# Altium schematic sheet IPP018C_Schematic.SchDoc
size 558 x 431 mm; Date: Not shown in title block; ApprovedBy: Not shown in title block; CheckedBy: Not shown in title block; Author: Not shown in title block; CompanyName: Not shown in title block; DrawnBy: Brandon Beader; Engineer: Not shown in title block; Organization: Not shown in title block; Address1: Not shown in title block; Address2: Not shown in title block; Address3: Not shown in title block; Address4: Not shown in title block; DocumentNumber: 2; Revision: Use project parameter SCH_Rev; SheetNumber: 1; SheetTotal: 2; PageSetup: Record=PageOptions¦CenterHorizontal=True¦CenterVertical=True¦PrintScale=1.00¦XCorrection=1.00¦YCorrection=1.00¦PrintKind=0¦BorderSize=5000000¦LeftOffset=0¦BottomOffset=0¦Orientation=2¦PaperLength=1000¦PaperWidth=1000¦Scale=100¦PaperSource=15¦PrintQuality=600¦MediaType=1¦DitherType=10¦PaperKind=Letter¦PrintScaleMode=1
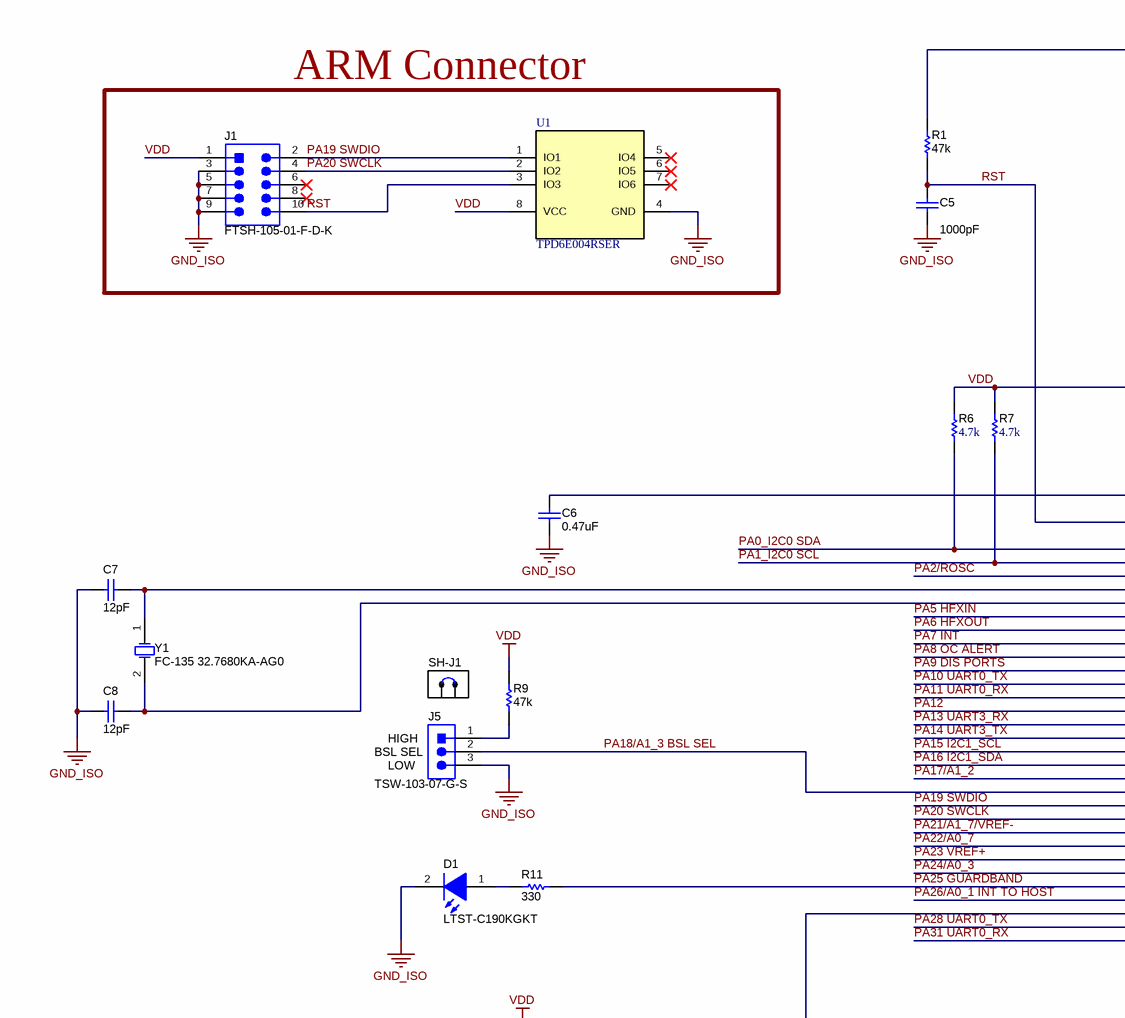
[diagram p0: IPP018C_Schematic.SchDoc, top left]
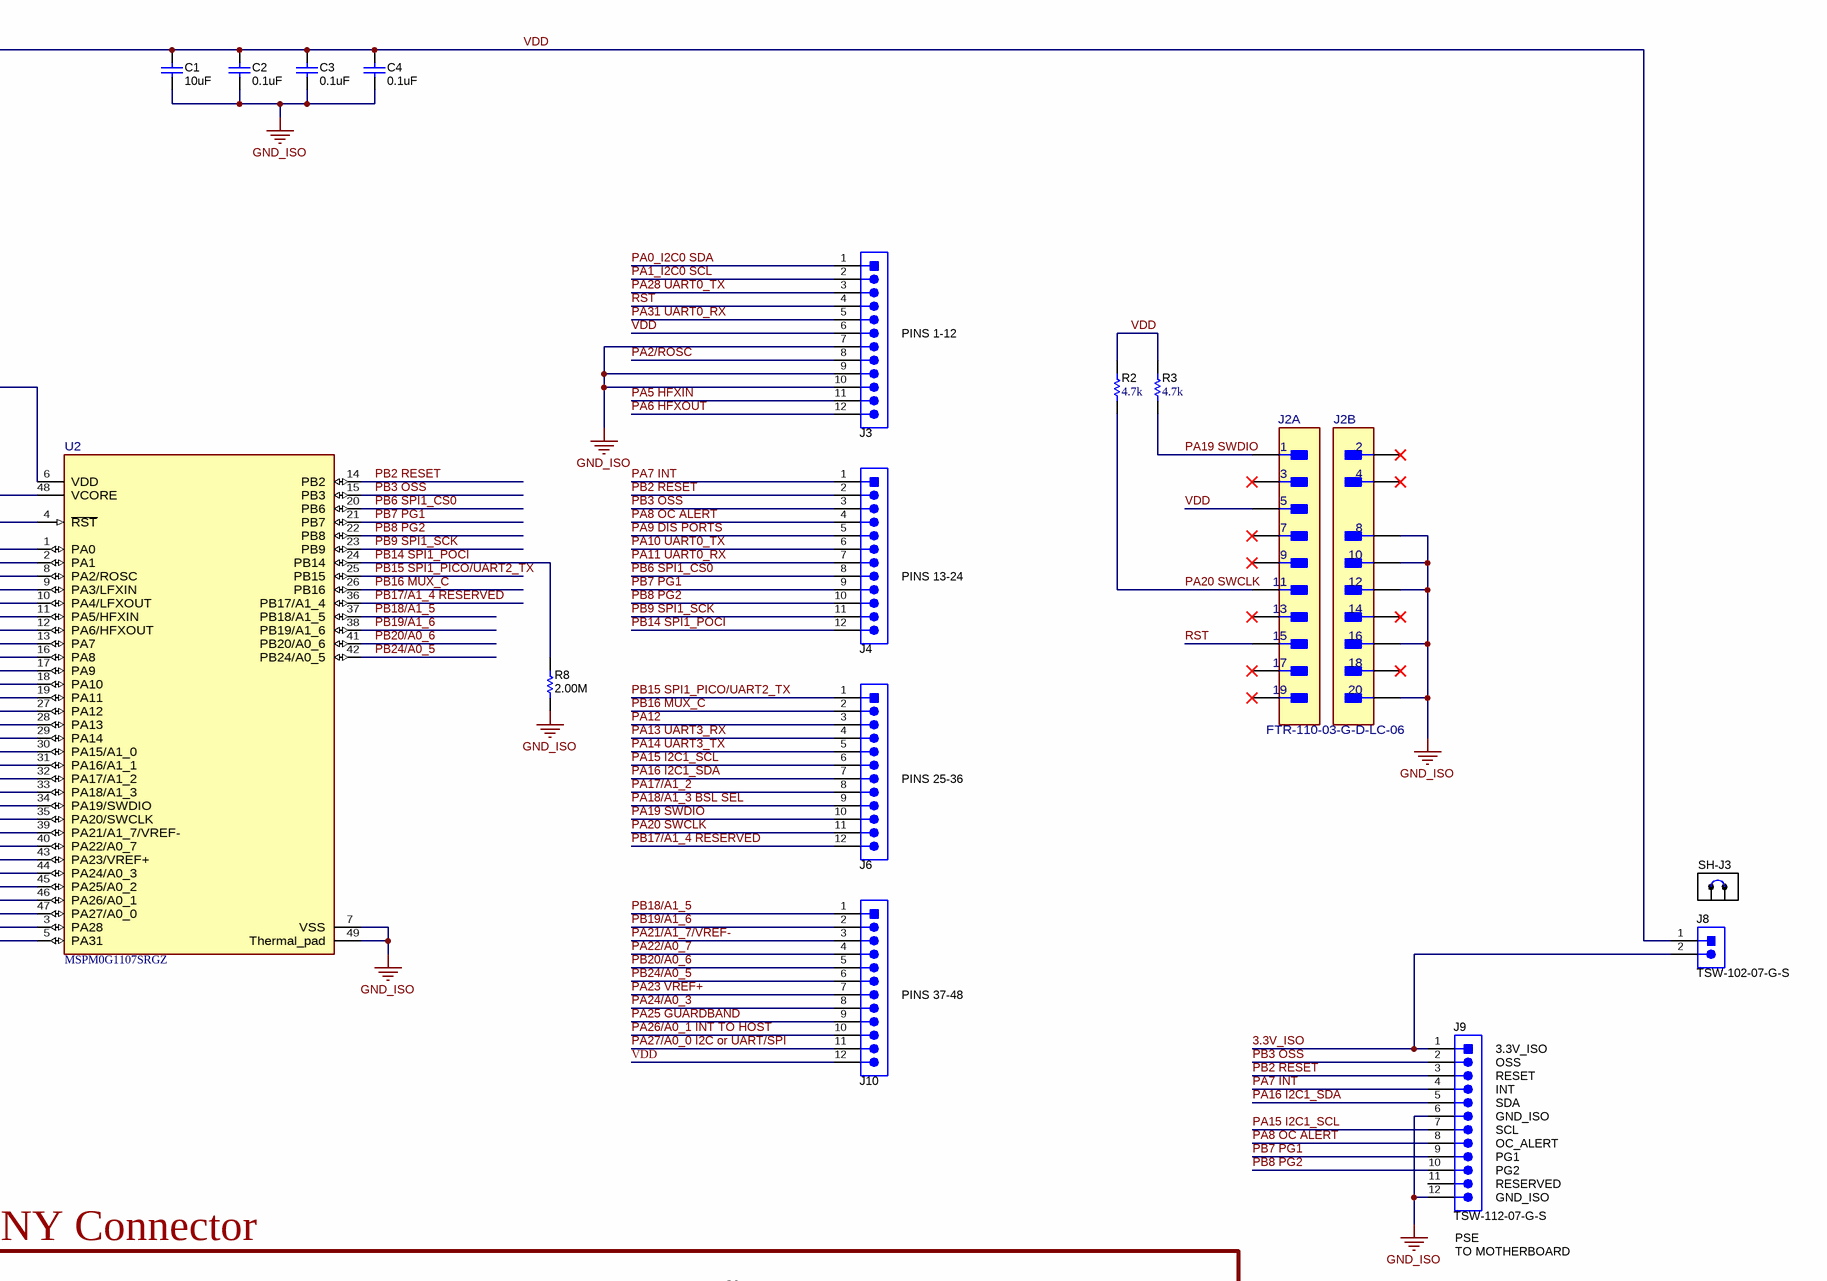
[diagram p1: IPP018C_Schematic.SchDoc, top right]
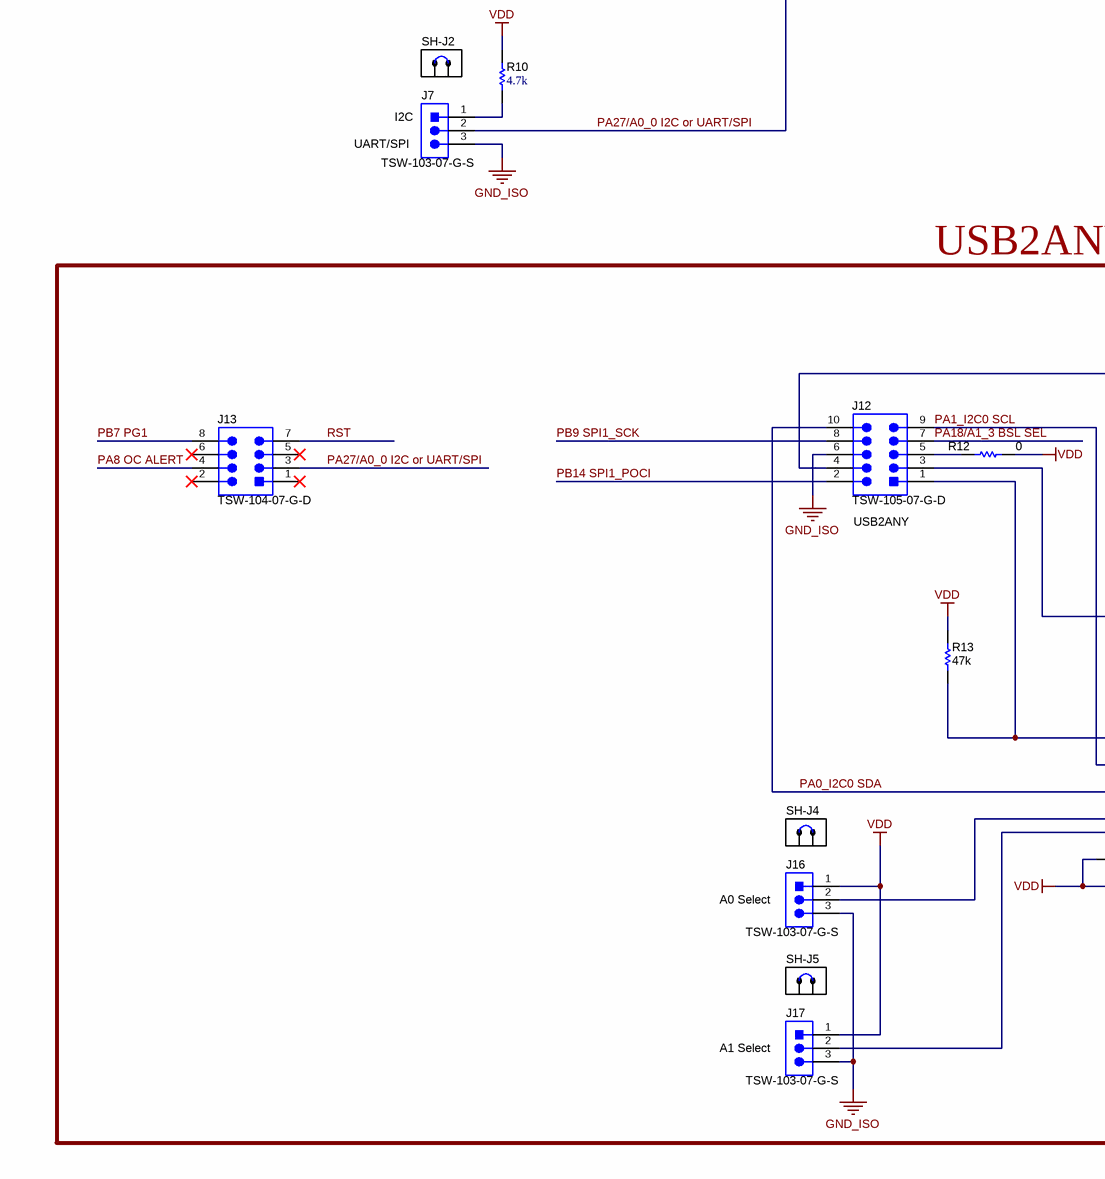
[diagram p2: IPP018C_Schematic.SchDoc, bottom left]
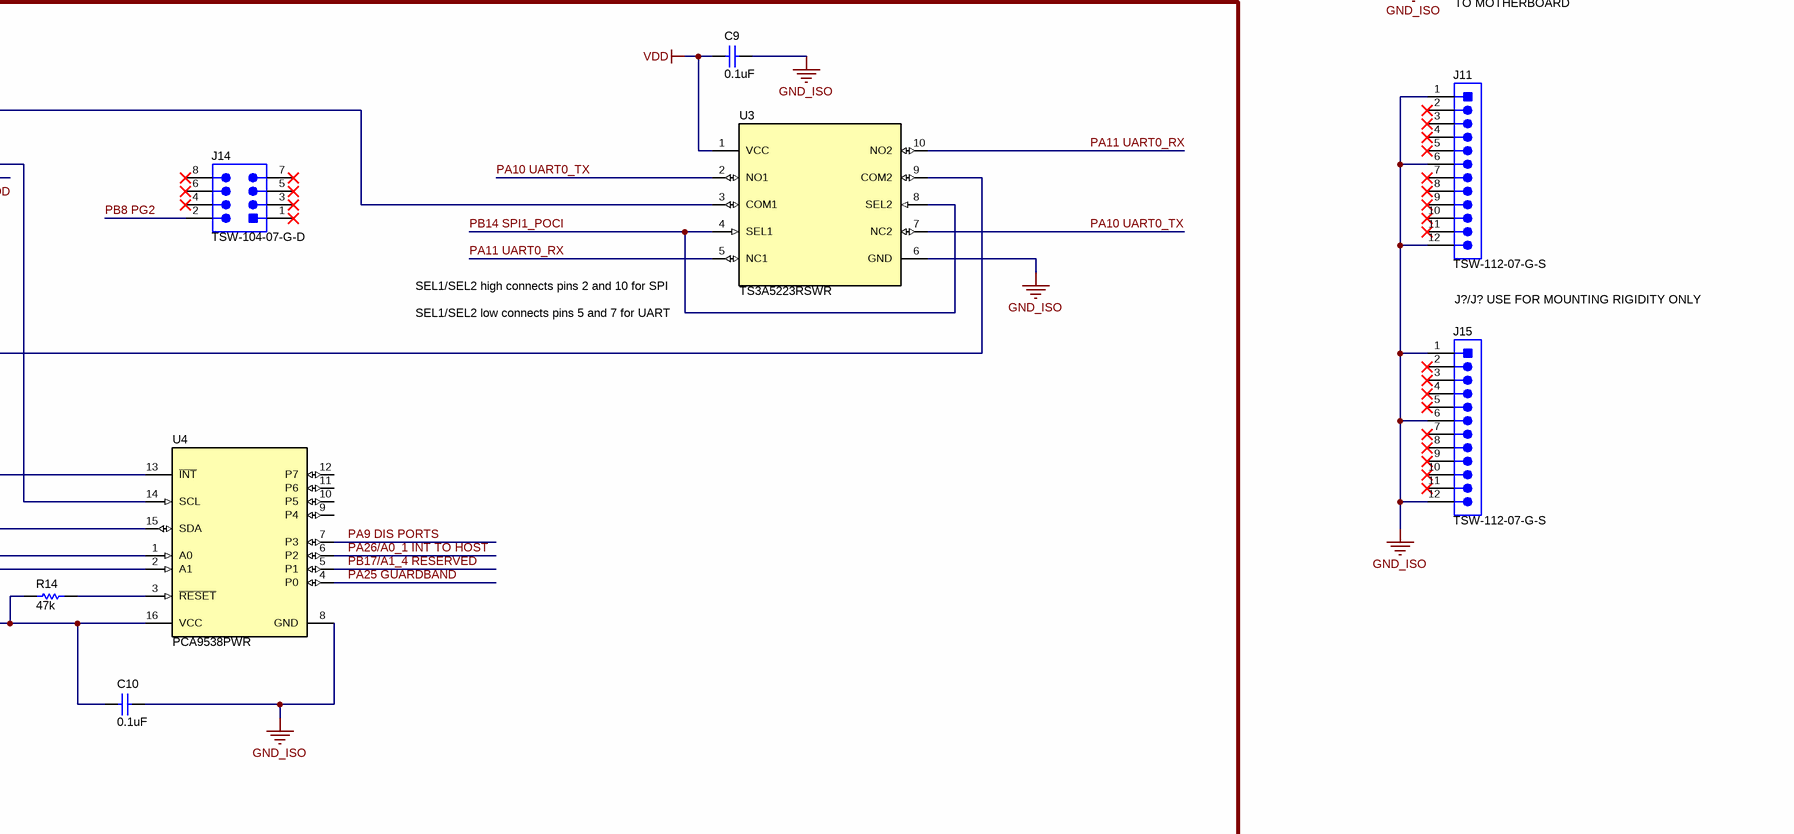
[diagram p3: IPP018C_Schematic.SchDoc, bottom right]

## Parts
C1  ValueDisplayed: 10uF  [0805L]  (hidden comment: 885012207026)
C2  ValueDisplayed: 0.1uF  [0603L]  (hidden comment: 885012206046)
C3  ValueDisplayed: 0.1uF  [0603L]  (hidden comment: 885012206046)
C4  ValueDisplayed: 0.1uF  [0603L]  (hidden comment: 885012206046)
C5  ValueDisplayed: 1000pF  [0603L]  (hidden comment: 885012206083)
C6  ValueDisplayed: 0.47uF  [0603L]  (hidden comment: GCM188R71C474KA55D)
C7  ValueDisplayed: 12pF  [0402L]  (hidden comment: CL05C120JB5NNNC)
C8  ValueDisplayed: 12pF  [0402L]  (hidden comment: CL05C120JB5NNNC)
C9  ValueDisplayed: 0.1uF  [0603L]  (hidden comment: 885012206046)
C10  ValueDisplayed: 0.1uF  [0603L]  (hidden comment: 885012206046)
D1  LTST-C190KGKT  [LED_LTST-C190_G]
J1  FTSH-105-01-F-D-K  [Samtec_FTSH-105-01-x-D-K]
J2  FTR-110-03-G-D-LC-06  [FP-FTR-110-03-G-D-LC-06_HDR19-MFG]  (value not drawn)  (parts A,B of 2)
J3  TSW-112-07-G-S  [TSW-112-07-G-S]  (value not drawn)
J4  TSW-112-07-G-S  [TSW-112-07-G-S]  (value not drawn)
J5  TSW-103-07-G-S  [TSW-103-07-G-S]
J6  TSW-112-07-G-S  [TSW-112-07-G-S]  (value not drawn)
J7  TSW-103-07-G-S  [TSW-103-07-G-S]
J8  TSW-102-07-G-S  [TSW-102-07-G-S]
J9  TSW-112-07-G-S  [TSW-112-07-G-S]
J10  TSW-112-07-G-S  [TSW-112-07-G-S]  (value not drawn)
J11  TSW-112-07-G-S  [TSW-112-07-G-S]
J12  TSW-105-07-G-D  [TSW-105-07-G-D]
J13  TSW-104-07-G-D  [TSW-104-07-G-D]
J14  TSW-104-07-G-D  [TSW-104-07-G-D]
J15  TSW-112-07-G-S  [TSW-112-07-G-S]
J16  TSW-103-07-G-S  [TSW-103-07-G-S]
J17  TSW-103-07-G-S  [TSW-103-07-G-S]
R1  ValueDisplayed: 47k  [0402L]  (hidden comment: CRCW040247K0JNED)
R2  ValueDisplayed: 4.7k  [0402]  (hidden comment: CRCW04024K70JNED)
R3  ValueDisplayed: 4.7k  [0402]  (hidden comment: CRCW04024K70JNED)
R6  ValueDisplayed: 4.7k  [0402]  (hidden comment: CRCW04024K70JNED)
R7  ValueDisplayed: 4.7k  [0402]  (hidden comment: CRCW04024K70JNED)
R8  ValueDisplayed: 2.00M  [0402L]  (hidden comment: CRCW04022M00FKED)
R9  ValueDisplayed: 47k  [0402L]  (hidden comment: CRCW040247K0JNED)
R10  ValueDisplayed: 4.7k  [0402]  (hidden comment: CRCW04024K70JNED)
R11  ValueDisplayed: 330  [0402L]  (hidden comment: CRCW0402330RJNED)
R12  ValueDisplayed: 0  [0402L]  (hidden comment: ERJ-2GE0R00X)
R13  ValueDisplayed: 47k  [0402L]  (hidden comment: CRCW040247K0JNED)
R14  ValueDisplayed: 47k  [0402L]  (hidden comment: CRCW040247K0JNED)
SH-J1  SPC02SYAN  [SPC02SYAN]  (value not drawn)
SH-J2  SPC02SYAN  [SPC02SYAN]  (value not drawn)
SH-J3  SPC02SYAN  [SPC02SYAN]  (value not drawn)
SH-J4  SPC02SYAN  [SPC02SYAN]  (value not drawn)
SH-J5  SPC02SYAN  [SPC02SYAN]  (value not drawn)
U1  TPD6E004RSER  [RSE0008A]
U2  MSPM0G1107SRGZ  [RGZ0048B-MFG]
U3  TS3A5223RSWR  [RSW0010A]
U4  PCA9538PWR  [PW0016A_L]
Y1  FC-135 32.7680KA-AG0  [Epson_FC-135]

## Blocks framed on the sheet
ARM Connector: J1 U1
USB2ANY Connector: C9 C10 J12-J14 J16 J17 R12-R14 SH-J4 SH-J5 U3 U4

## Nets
GND_ISO: C1.1 C2.1 C3.1 C4.1 C5.2 C6.1 C7.2 C8.2 C9.1 C10.1 D1.2(K) J1.3 J1.5 J1.7 J1.9 J2.8 J2.10 J2.12 J2.16 J2.20 J3.7 J3.9 J3.10 J5.3 J7.3 J9.6 J9.12 J11.1 J11.6 J11.12 J12.6 J15.1 J15.6 J15.12 J16.3 J17.3 R8.2 U1.4(GND) U2.7(VSS) U2.49(Thermal_pad) U3.6(GND) U4.8(GND)
VDD: C1.2 C2.2 C3.2 C4.2 C9.2 C10.2 J1.1 J2.5 J3.6 J8.1 J10.12 J16.1 J17.1 R1.2 R2.1 R3.1 R6.2 R7.2 R9.2 R10.1 R12.1 R13.2 R14.2 U1.8(VCC) U2.6(VDD) U3.1(VCC) U4.16(VCC)
3.3V_ISO: J8.2 J9.1
PA0_I2C0 SDA: J3.1 J12.10 R6.1 U2.1(PA0) U4.15(SDA)
PA1_I2C0 SCL: J3.2 J12.9 R7.1 U2.2(PA1) U4.14(SCL)
PA2/ROSC: J3.8 U2.8(PA2/ROSC)
PA5 HFXIN: J3.11 U2.11(PA5/HFXIN)
PA6 HFXOUT: J3.12 U2.12(PA6/HFXOUT)
PA7 INT: J4.1 J9.4 U2.13(PA7)
PA8 OC ALERT: J4.4 J9.8 J13.4 U2.16(PA8)
PA9 DIS PORTS: J4.5 U2.17(PA9) U4.7(P3)
PA10 UART0_TX: J4.6 U2.18(PA10) U3.2(NO1) U3.7(NC2)
PA11 UART0_RX: J4.7 U2.19(PA11) U3.5(NC1) U3.10(NO2)
PA12: J6.3 U2.27(PA12)
PA13 UART3_RX: J6.4 U2.28(PA13)
PA14 UART3_TX: J6.5 U2.29(PA14)
PA15 I2C1_SCL: J6.6 J9.7 U2.30(PA15/A1_0)
PA16 I2C1_SDA: J6.7 J9.5 U2.31(PA16/A1_1)
PA17/A1_2: J6.8 U2.32(PA17/A1_2)
PA18/A1_3 BSL SEL: J5.2 J6.9 J12.7 U2.33(PA18/A1_3)
PA19 SWDIO: J1.2 J2.1 J6.10 R3.2 U1.1(IO1) U2.34(PA19/SWDIO)
PA20 SWCLK: J1.4 J2.11 J6.11 R2.2 U1.2(IO2) U2.35(PA20/SWCLK)
PA21/A1_7/VREF-: J10.3 U2.39(PA21/A1_7/VREF-)
PA22/A0_7: J10.4 U2.40(PA22/A0_7)
PA23 VREF+: J10.7 U2.43(PA23/VREF+)
PA24/A0_3: J10.8 U2.44(PA24/A0_3)
PA25 GUARDBAND: J10.9 R11.2 U2.45(PA25/A0_2) U4.4(P0)
PA26/A0_1 INT TO HOST: J10.10 U2.46(PA26/A0_1) U4.6(P2)
PA27/A0_0 I2C or UART/SPI: J7.2 J10.11 J13.3 U2.47(PA27/A0_0)
PA28 UART0_TX: J3.3 U2.3(PA28)
PA31 UART0_RX: J3.5 U2.5(PA31)
PB2 RESET: J4.2 J9.3 U2.14(PB2)
PB3 OSS: J4.3 J9.2 U2.15(PB3)
PB6 SPI1_CS0: J4.8 U2.20(PB6)
PB7 PG1: J4.9 J9.9 J13.8 U2.21(PB7)
PB8 PG2: J4.10 J9.10 J14.2 U2.22(PB8)
PB9 SPI1_SCK: J4.11 J12.8 U2.23(PB9)
PB14 SPI1_POCI: J4.12 J12.2 R8.1 U2.24(PB14) U3.4(SEL1) U3.8(SEL2)
PB15 SPI1_PICO/UART2_TX: J6.1 U2.25(PB15)
PB16 MUX_C: J6.2 U2.26(PB16)
PB17/A1_4 RESERVED: J6.12 U2.36(PB17/A1_4) U4.5(P1)
PB18/A1_5: J10.1 U2.37(PB18/A1_5)
PB19/A1_6: J10.2 U2.38(PB19/A1_6)
PB20/A0_6: J10.5 U2.41(PB20/A0_6)
PB24/A0_5: J10.6 U2.42(PB24/A0_5)
RST: C5.1 J1.10 J2.15 J3.4 J13.7 R1.1 U1.3(IO3) U2.4(~{RST})
NetC6_2: C6.2 U2.48(VCORE)
NetC7_1: C7.1 U2.9(PA3/LFXIN) Y1.1(OSC1)
NetC8_1: C8.1 U2.10(PA4/LFXOUT) Y1.2(OSC2)
NetD1_1: D1.1(A) R11.1
NetJ5_1: J5.1 R9.1
NetJ7_1: J7.1 R10.2
NetJ12_1: J12.1 R13.1 U4.13(~{INT})
NetJ12_3: J12.3 U3.9(COM2)
NetJ12_4: J12.4 U3.3(COM1)
NetJ12_5: J12.5 R12.2
NetJ16_2: J16.2 U4.1(A0)
NetJ17_2: J17.2 U4.2(A1)
NetR14_1: R14.1 U4.3(~{RESET})

Not connected (* = marked no-connect by the designer): J1 6* 8*; J2 2* 3* 4* 7* 9* 13* 14* 17* 18* 19*; J9 11; J11 2* 3* 4* 5* 7* 8* 9* 10* 11*; J13 1* 2* 5* 6*; J14 1* 3* 4* 5* 6* 7* 8*; J15 2* 3* 4* 5* 7* 8* 9* 10* 11*; U1 5(IO4)* 6(IO5)* 7(IO6)*; U4 9(P4) 10(P5) 11(P6) 12(P7)

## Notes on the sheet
- (near J3) PINS 1-12
- (near J4) PINS 13-24
- (near J5) BSL SEL
- HIGH
- (near J5) LOW
- (near J6) PINS 25-36
- (near J10) PINS 37-48
- (near J7) I2C
- (near J9) 3.3V_ISO
- (near J9) OSS
- (near J9) RESET
- (near J9) INT
- (near J9) SDA
- (near J7) UART/SPI
- (near J9) GND_ISO
- (near J9) SCL
- (near J9) OC_ALERT
- (near J9) PG1
- (near J9) PG2
- (near J9) PSE
- (near J9) RESERVED
- (near J9) TO MOTHERBOARD
- (near J12) USB2ANY
- SEL1/SEL2 high connects pins 2 and 10 for SPI
- SEL1/SEL2 low connects pins 5 and 7 for UART
- J?/J? USE FOR MOUNTING RIGIDITY ONLY
- (near J16) A0 Select
- (near J17) A1 Select

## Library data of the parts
C1 = CMP-0007691-2: CAP, CERM, 10 uF, 10 V, +/- 10%, X7R, 0805; Manufacturer: Wurth Elektronik; TaMin_C: -55°C; Polarized: N; SizeAreaWB_mm2: 6.75; Value1: Unknown; U/M: EA; Value: 10uF; TaMax_C: 125°C; SizeZ_mm: 1.45; SizeX_mm: 2; SizeY_mm: 1.25; Cap_Case: 0805; Value2: 10V; SizeArea_mm2: 2.5; CompType: Capacitor; Cap_F: 10µF; AEC Category: Q200
C2-C4 C9 C10 = CMP-0006829-4: CAP, CERM, 0.1 uF, 16 V, +/- 10%, X7R, 0603; Manufacturer: Wurth Elektronik; TaMin_C: -55°C; Polarized: N; SizeAreaWB_mm2: 4.68; Value1: Unknown; U/M: EA; Value: 0.1uF; TaMax_C: 125°C; SizeZ_mm: 1; SizeX_mm: 1.6; SizeY_mm: 0.8; Cap_Case: 0603; Value2: 16V; SizeArea_mm2: 1.28; CompType: Capacitor; Cap_F: 100nF; AEC Category: Q200
C5 = CMP-0064933-4: CAP, CERM, 1000 pF, 50 V,+/- 10%, X7R, 0603; Manufacturer: Wurth Elektronik; TaMin_C: -55°C; Polarized: N; SizeAreaWB_mm2: 4.68; Value1: Unknown; U/M: EA; Value: 1000pF; TaMax_C: 125°C; SizeZ_mm: 1; SizeX_mm: 1.6; SizeY_mm: 0.8; Cap_Case: 0603; Value2: 50V; SizeArea_mm2: 1.28; CompType: Capacitor; Cap_F: 1nF; AEC Category: Q200
C6 = CMP-0007138-4: CAP, CERM, 0.47 uF, 16 V, +/- 10%, X7R, AEC-Q200 Grade 1, 0603; Manufacturer: MuRata; TaMin_C: -55°C; Polarized: N; SizeAreaWB_mm2: 4.68; Value1: Unknown; U/M: EA; Value: 0.47uF; TaMax_C: 125°C; SizeZ_mm: 1; SizeX_mm: 1.6; SizeY_mm: 0.8; Cap_Case: 0603; Value2: 16V; SizeArea_mm2: 1.28; CompType: Capacitor; AEC Qualified: Y; Cap_F: 470nF; AEC Category: Q200
C7 C8 = CMP-0006345-2: CAP, CERM, 12 pF, 50 V, +/- 5%, C0G/NP0, 0402; Manufacturer: Samsung Electro-Mechanics; TaMin_C: -55°C; Polarized: N; SizeAreaWB_mm2: 3; Value1: Unknown; U/M: EA; Value: 12pF; TaMax_C: 125°C; SizeZ_mm: 0.6; SizeX_mm: 1; SizeY_mm: 0.5; Cap_Case: 0402; Value2: 50V; CompType: Capacitor; AEC Category: Q200
D1 = CMP-0002840-2: LED, Green, SMD; Manufacturer: Lite-On; Value1: W; Io_A: 30mA; Value2: 2V; Tjmax_C: 85°C; Type: AlInGaP
J1 = CMP-0075533-2: Header, 1.27 mm, 5x2, Gold, TH; Manufacturer: Samtec; Pitch_mm: 1.27; Gender: Male; Green_REACh: Passed; Shrouded: Y; Green_Lifecycle: Active; Row_Count: 2
J2 = CMP-0092655-1: Manufacturer: Samtec; Conn Gender: Male; Row_Count: 2; ContactFinish: Gold,Nickel; Is Female: no; Conn Orientation: Vertical; SizeZ_mm: 7.58mm; Current_A: 3.1A; Standoff Height: 1mm; DUT-Pitch_mm: 1.27mm
J3 J4 J6 J9-J11 J15 = CMP-0075424-1: Header, 100mil, 12x1, Gold, TH; Manufacturer: Samtec; Pitch_mm: 2.54; Cert_VDE: N; Gender: Male; Cert_CSA: Y; Current_A: 6.3A; Voltage_V: 550V; CT: False; Row_Count: 1; CNHeader: True
J5 J7 J16 J17 = CMP-0075407-2: Header, 100mil, 3x1, Gold, TH; Manufacturer: Samtec; Pitch_mm: 2.54; Cert_VDE: N; Gender: Male; Cert_CSA: Y; Voltage_V: 550V; Green_REACh: Passed; Current_A: 6.3A; Green_Lifecycle: Active; Row_Count: 1
J8 = CMP-0075405-2: Header, 100mil, 2x1, Gold, TH; Manufacturer: Samtec; Pitch_mm: 2.54; Cert_VDE: N; Gender: Male; Cert_CSA: Y; Voltage_V: 550V; Green_REACh: Passed; Current_A: 6.3A; Green_Lifecycle: Active; Row_Count: 1
J12 = CMP-0075410-2: Header, 100mil, 5x2, Gold, TH; Manufacturer: Samtec; Green_Lifecycle: Active; Green_REACh: Passed; Cert_CSA: Y; Cert_CULUS: N; Current_A: 6.3A; Gender: Male; Pitch_mm: 2.54; Row_Count: 2; Voltage_V: 550V
J13 J14 = CMP-0075408-2: Header, 100mil, 4x2, Gold, TH; Manufacturer: Samtec; Pitch_mm: 2.54; Cert_VDE: N; Gender: Male; Cert_CSA: Y; Voltage_V: 550V; Green_REACh: Passed; Current_A: 6.3A; Green_Lifecycle: Active; Row_Count: 2
R1 R9 = CMP-0026935-3: RES, 47 k, 5%, 0.063 W, AEC-Q200 Grade 0, 0402; Manufacturer: Vishay-Dale; Power_W: 63mW; TempCo: 200 ppm/C; Value_Code: 47k0; Value: 47k; EIA_Code: E24; SizeX_mm: 1; SizeY_mm: 0.5; SizeZ_mm: 0.6; Value2: 0.063W; AEC Qualified: Y; VDC_V: 50V; AEC Category: Q200; AEC Grade: 0
R2 R3 R6 R7 R10 = CMP-0026938-5: RES, 4.7 k, 5%, 0.063 W, AEC-Q200 Grade 0, 0402; Manufacturer: Vishay-Dale; Power_W: 63mW; TempCo: 200 ppm/C; Value_Code: 4k70; Value: 4.7k; EIA_Code: E24; SizeX_mm: 1; SizeY_mm: 0.5; SizeZ_mm: 0.6; Value2: 0.063W; AEC Qualified: Y; VDC_V: 50V; AEC Category: Q200; AEC Grade: 0
R8 = CMP-0026245-2: RES, 2.00 M, 1%, 0.063 W, AEC-Q200 Grade 0, 0402; Manufacturer: Vishay-Dale; Power_W: 63mW; TempCo: 100 ppm/C; Value_Code: 2M00; Value: 2.00Meg; EIA_Code: E96; Res_ohm: 2M; SizeX_mm: 1; SizeY_mm: 0.5; SizeZ_mm: 0.6; Value2: 0.063W; CompType: Resistor; AEC Qualified: Y; VDC_V: 50V; AEC Category: Q200; AEC Grade: 0
R11 = CMP-0026906-3: RES, 330, 5%, 0.063 W, AEC-Q200 Grade 0, 0402; Manufacturer: Vishay-Dale; Power_W: 63mW; TempCo: 200 ppm/C; Value_Code: 330R; Value: 330; EIA_Code: E24; SizeX_mm: 1; SizeY_mm: 0.5; SizeZ_mm: 0.6; Value2: 0.063W; CompType: Resistor; AEC Qualified: Y; VDC_V: 50V; AEC Category: Q200; AEC Grade: 0
R12 = CMP-0026992-3: RES, 0, 5%, 0.1 W, AEC-Q200 Grade 0, 0402; Manufacturer: Panasonic; Power_W: 100mW; TempCo: 600 ppm/C; Value_Code: 0000; Value: 0; EIA_Code: E24; SizeX_mm: 1; SizeY_mm: 0.5; SizeZ_mm: 0.6; Value2: 0.1W; AEC Qualified: Y; VDC_V: 50V; AEC Category: Q200; SizeAreaWB_mm2: 3
R13 R14 = CMP-0026935-3: RES, 47 k, 5%, 0.063 W, AEC-Q200 Grade 0, 0402; Manufacturer: Vishay-Dale; Power_W: 63mW; TempCo: 200 ppm/C; Value_Code: 47k0; Value: 47k; EIA_Code: E24; SizeX_mm: 1; SizeY_mm: 0.5; SizeZ_mm: 0.6; Value2: 0.063W; CompType: Resistor; AEC Qualified: Y; VDC_V: 50V; AEC Category: Q200; AEC Grade: 0
SH-J1-SH-J5 = CMP-0003642-1: Shunt, 100mil, Flash Gold, Black; Manufacturer: Sullins Connector Solutions; Value: 1x2; Note: You can "mate" this to a header by matching the designator.  i.e. use SH-J3 for header J3
U1 = CMP-0043125-4: Low-Capacitance 6-Channel +/-15 kV ESD Protection Array for High-Speed Data Interfaces, RSE0008A (UQFN-8); Manufacturer: Texas Instruments; IO Leakage Current(nA): 1; IO Capacitance(Typ)(pF): 1.6; 1394 / Firewire: TRUE; Eco-Plan: Green (RoHS & no Sb/Br); SubFamily: ESD Solution; Breakdown Voltage(Min)(V): 6; IEC 61000-4-2 Air-Gap(+/- kV): 12; IEC 61000-4-2 Contact(+/- kV): 8; AEC Category: Q200; AEC Qualified: N; CompType: IC; SizeAreaWB_mm2: 6.25; SizeArea_mm2: 2.25; SizeX_mm: 1.5; SizeZ_mm: 0.6
U2 = CMP-0097891-1: Mixed-Signal Microcontrollers; Manufacturer: Texas Instruments; TJmax_C: +130°C; Number Of Uart Channels: 4; Min Supply Voltage: 1.62V; SizeZ_mm: 1mm; Number Of A/D Converters: 2; Number Of Timers/Counters: 7; Core Architecture: ARM Cortex-M0+; Max Supply Voltage: 3.6V; Number Of I/Os: 44; TaMin_C: -40°C; Number Of Cores: 1; Memory Type: FLASH; Interface: I2C,SPI,UART,LIN,IrDA,SMBus,Other; Memory Size: 128KBytes; Frequency_Fixed: 80MHz; AEC Qualified: No; Ram Size: 32KBytes; Standoff Height: 0mm; Data Bus Width: 32bits; TaMax_C: +125°C; Number Of Adc Channels: 15
U3 = CMP-0085520-1: 0.5Ω Dual SPDT Bidirectional Analog Switch, RSW0010A (UQFN-10); Manufacturer: Texas Instruments; Rating: Catalog; SizeY_mm: 1.8; AEC Qualified: N; SizeZ_mm: 0.55; CompType: IC; SizeArea_mm2: 2.52; AEC Category: Q200; SizeAreaWB_mm2: 6.72; SizeX_mm: 1.4
U4 = CMP-0043202-2: Remote 8-Bit I2C and SMBus Low-Power I/O Expander With Interrupt Output, Reset, and Config Registers, PW0016A (TSSOP-16); Manufacturer: Texas Instruments; AEC Category: Q200; Interrupt Output: Yes; Max Frequency(kHz): 400; VCC(Max)(V): 5.5; fSCLK(Max)(MHz): 0.1, 0.4; Rating: Catalog; CompType: IC; I2C Address: 1110 0xx; AEC Qualified: N; Vcc range(V): 2.3 to 5.5; Technology Family: I2C, SMBus; # of I/Os: 8; VCC(Min)(V): 2.3
Y1 = CMP-0079303-1: Crystal, 32.768 KHz, 20 ppm, 7 pF, SMD; Manufacturer: Epson; TaMin_C: -40°C; Frequency Tolerance: 20 ppm; Load Capacitance: 7 pF; TaMax_C: 85°C; AEC Qualified: N; AEC Category: Q200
